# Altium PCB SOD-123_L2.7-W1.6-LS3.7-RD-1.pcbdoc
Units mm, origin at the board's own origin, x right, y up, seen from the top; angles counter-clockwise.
Board outline 17.3 x 14.65 mm, 2 copper layers (Top Layer, Bottom Layer), stack 0 mm thick; 1 components, 0 nets, 2 pads, 0 vias.
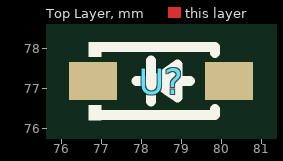
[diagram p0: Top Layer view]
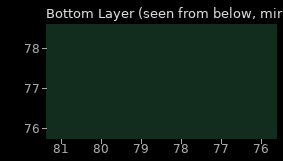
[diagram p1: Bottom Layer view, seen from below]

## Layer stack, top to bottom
Top Layer: signal copper (thickness not stored)
Bottom Layer: signal copper (thickness not stored)

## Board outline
87.15,69.85 69.85,69.85 69.85,84.504 87.15,84.504

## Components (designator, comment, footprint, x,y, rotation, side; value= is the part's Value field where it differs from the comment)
U? "" SOD-123_L2.7-W1.6-LS3.7-RD-1 78.5,77.177 r0 top

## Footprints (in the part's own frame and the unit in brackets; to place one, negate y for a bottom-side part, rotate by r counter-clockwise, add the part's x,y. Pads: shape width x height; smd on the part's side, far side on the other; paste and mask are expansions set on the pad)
SOD-123_L2.7-W1.6-LS3.7-RD-1 [mm]
  rect 1.2x0.95 smd: 1(-1.7,0) 2(1.7,0)
  silkscreen extent -1.81,-0.98 1.35,0.98

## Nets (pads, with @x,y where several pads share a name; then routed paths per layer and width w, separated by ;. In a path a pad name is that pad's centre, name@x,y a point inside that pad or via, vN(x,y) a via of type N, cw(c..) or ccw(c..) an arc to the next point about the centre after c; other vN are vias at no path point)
pads on no net: U?.1 U?.2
